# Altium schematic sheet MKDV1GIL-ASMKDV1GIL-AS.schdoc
size 127 x 101 mm
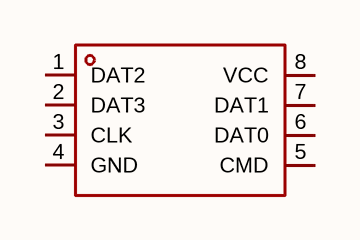
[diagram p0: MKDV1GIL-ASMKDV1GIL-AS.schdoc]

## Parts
U?  mkdv1gil-as  [LGA-8_L6.0-W8.0-P1.27-BL]  (value not drawn)

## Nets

Not connected (* = marked no-connect by the designer): U? 1(DAT2) 2(DAT3) 3(CLK) 4(GND) 5(CMD) 6(DAT0) 7(DAT1) 8(VCC)

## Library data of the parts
U? = mkdv1gil-as: 存储容量:1Gbit;时钟频率(fc):50MHz;工作电压:2.7V~3.6V;; Manufacturer: MK(米客方德); AddInBom: yes; ModelId: 1f88d973af574684b0007f41a35ee8d9; ModelName: LGA-8_L6.0-W8.0-H0.8-P1.27; ModelTransform: 314.96,236.22,0,90,0,0,0,0.005,0; Memory Size: 1Gbit; Interface: SD接口；SPI; Clock Frequency: 50MHz; Standby Supply Current: 50uA; ECC: 有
